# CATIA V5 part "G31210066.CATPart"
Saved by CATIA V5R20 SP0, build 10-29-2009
Part number: G31210066
Revision: 5
Definition: design
Nomenclature: G31210066
Source: made
Description: NOT SPECIFIED
Bounding box of the stored display mesh (mm): x -5 to 66, y -8 to 8, z -8 to 8
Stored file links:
  C:\Users\Raffaele\Desktop\3D X SITO CF\BOLEX\23-BUSH REF 312\G31210066.CATPart

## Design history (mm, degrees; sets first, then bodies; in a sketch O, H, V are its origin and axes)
Body1 "MANIFOLD_SOLID_BREP #14607" (main body)
  Solid1: solid without history
Body2 "MANIFOLD_SOLID_BREP #14750"
  Solid2: solid without history
Body3 "MANIFOLD_SOLID_BREP #14893"
  Solid3: solid without history
Body4 "MANIFOLD_SOLID_BREP #15036"
  Solid4: solid without history
Body5 "MANIFOLD_SOLID_BREP #15179"
  Solid5: solid without history
Body6 "MANIFOLD_SOLID_BREP #15324"
  Solid6: solid without history
Body7 "MANIFOLD_SOLID_BREP #15469"
  Solid7: solid without history
Body8 "MANIFOLD_SOLID_BREP #15614"
  Solid8: solid without history
Body9 "MANIFOLD_SOLID_BREP #15759"
  Solid9: solid without history
Body10 "MANIFOLD_SOLID_BREP #15904"
  Solid10: solid without history
Body11 "MANIFOLD_SOLID_BREP #16049"
  Solid11: solid without history
Body12 "MANIFOLD_SOLID_BREP #16194"
  Solid12: solid without history
Body13 "MANIFOLD_SOLID_BREP #16339"
  Solid13: solid without history
Body14 "MANIFOLD_SOLID_BREP #16484"
  Solid14: solid without history
Body15 "MANIFOLD_SOLID_BREP #16629"
  Solid15: solid without history
Body16 "MANIFOLD_SOLID_BREP #16774"
  Solid16: solid without history
Body17 "MANIFOLD_SOLID_BREP #16919"
  Solid17: solid without history
Body18 "MANIFOLD_SOLID_BREP #17064"
  Solid18: solid without history
Body19 "MANIFOLD_SOLID_BREP #17209"
  Solid19: solid without history
Body20 "MANIFOLD_SOLID_BREP #17354"
  Solid20: solid without history
Body21 "MANIFOLD_SOLID_BREP #17499"
  Solid21: solid without history
Body22 "MANIFOLD_SOLID_BREP #17644"
  Solid22: solid without history
Body23 "MANIFOLD_SOLID_BREP #17789"
  Solid23: solid without history
Body24 "MANIFOLD_SOLID_BREP #17934"
  Solid24: solid without history
Body25 "MANIFOLD_SOLID_BREP #18079"
  Solid25: solid without history
Body26 "MANIFOLD_SOLID_BREP #18224"
  Solid26: solid without history
Body27 "MANIFOLD_SOLID_BREP #18369"
  Solid27: solid without history
Body28 "MANIFOLD_SOLID_BREP #18514"
  Solid28: solid without history
Body29 "MANIFOLD_SOLID_BREP #18659"
  Solid29: solid without history
Body30 "MANIFOLD_SOLID_BREP #18804"
  Solid30: solid without history
Body31 "MANIFOLD_SOLID_BREP #18949"
  Solid31: solid without history
Body32 "MANIFOLD_SOLID_BREP #19094"
  Solid32: solid without history
Body33 "MANIFOLD_SOLID_BREP #19239"
  Solid33: solid without history
Body34 "MANIFOLD_SOLID_BREP #19384"
  Solid34: solid without history
Body35 "MANIFOLD_SOLID_BREP #19529"
  Solid35: solid without history
Body36 "MANIFOLD_SOLID_BREP #19674"
  Solid36: solid without history
Body37 "MANIFOLD_SOLID_BREP #19817"
  Solid37: solid without history
Body38 "MANIFOLD_SOLID_BREP #19960"
  Solid38: solid without history
Body39 "MANIFOLD_SOLID_BREP #20105"
  Solid39: solid without history
Body40 "MANIFOLD_SOLID_BREP #20250"
  Solid40: solid without history
Body41 "MANIFOLD_SOLID_BREP #20395"
  Solid41: solid without history
Body42 "MANIFOLD_SOLID_BREP #20540"
  Solid42: solid without history
Body43 "MANIFOLD_SOLID_BREP #20685"
  Solid43: solid without history
Body44 "MANIFOLD_SOLID_BREP #20830"
  Solid44: solid without history
Body45 "MANIFOLD_SOLID_BREP #20975"
  Solid45: solid without history
Body46 "MANIFOLD_SOLID_BREP #21120"
  Solid46: solid without history
Body47 "MANIFOLD_SOLID_BREP #21265"
  Solid47: solid without history
Body48 "MANIFOLD_SOLID_BREP #21410"
  Solid48: solid without history
Body49 "MANIFOLD_SOLID_BREP #21555"
  Solid49: solid without history
Body50 "MANIFOLD_SOLID_BREP #21700"
  Solid50: solid without history
Body51 "MANIFOLD_SOLID_BREP #21845"
  Solid51: solid without history
Body52 "MANIFOLD_SOLID_BREP #21990"
  Solid52: solid without history
Body53 "MANIFOLD_SOLID_BREP #22135"
  Solid53: solid without history
Body54 "MANIFOLD_SOLID_BREP #22280"
  Solid54: solid without history
Body55 "MANIFOLD_SOLID_BREP #22425"
  Solid55: solid without history
Body56 "MANIFOLD_SOLID_BREP #22570"
  Solid56: solid without history
Body57 "MANIFOLD_SOLID_BREP #22715"
  Solid57: solid without history
Body58 "MANIFOLD_SOLID_BREP #22860"
  Solid58: solid without history
Body59 "MANIFOLD_SOLID_BREP #23003"
  Solid59: solid without history
Body60 "MANIFOLD_SOLID_BREP #23146"
  Solid60: solid without history
Body61 "MANIFOLD_SOLID_BREP #23291"
  Solid61: solid without history
Body62 "MANIFOLD_SOLID_BREP #23436"
  Solid62: solid without history
Body63 "MANIFOLD_SOLID_BREP #23581"
  Solid63: solid without history
Body64 "MANIFOLD_SOLID_BREP #23726"
  Solid64: solid without history
Body65 "MANIFOLD_SOLID_BREP #23871"
  Solid65: solid without history
Body66 "MANIFOLD_SOLID_BREP #24016"
  Solid66: solid without history
Body67 "MANIFOLD_SOLID_BREP #24159"
  Solid67: solid without history
Body68 "MANIFOLD_SOLID_BREP #24302"
  Solid68: solid without history
Body69 "MANIFOLD_SOLID_BREP #24447"
  Solid69: solid without history
Body70 "MANIFOLD_SOLID_BREP #24592"
  Solid70: solid without history
Body71 "MANIFOLD_SOLID_BREP #24737"
  Solid71: solid without history
Body72 "MANIFOLD_SOLID_BREP #24882"
  Solid72: solid without history
Body73 "MANIFOLD_SOLID_BREP #25027"
  Solid73: solid without history
Body74 "MANIFOLD_SOLID_BREP #25172"
  Solid74: solid without history
Body75 "MANIFOLD_SOLID_BREP #25317"
  Solid75: solid without history
Body76 "MANIFOLD_SOLID_BREP #25462"
  Solid76: solid without history
Body77 "MANIFOLD_SOLID_BREP #25607"
  Solid77: solid without history
Body78 "MANIFOLD_SOLID_BREP #25752"
  Solid78: solid without history
Body79 "MANIFOLD_SOLID_BREP #25897"
  Solid79: solid without history
Body80 "MANIFOLD_SOLID_BREP #26042"
  Solid80: solid without history
Body81 "MANIFOLD_SOLID_BREP #26187"
  Solid81: solid without history
Body82 "MANIFOLD_SOLID_BREP #26332"
  Solid82: solid without history
Body83 "MANIFOLD_SOLID_BREP #26477"
  Solid83: solid without history
Body84 "MANIFOLD_SOLID_BREP #26622"
  Solid84: solid without history
Body85 "MANIFOLD_SOLID_BREP #26767"
  Solid85: solid without history
Body86 "MANIFOLD_SOLID_BREP #26912"
  Solid86: solid without history
Body87 "MANIFOLD_SOLID_BREP #27057"
  Solid87: solid without history
Body88 "MANIFOLD_SOLID_BREP #27202"
  Solid88: solid without history
Body89 "MANIFOLD_SOLID_BREP #27345"
  Solid89: solid without history
Body90 "MANIFOLD_SOLID_BREP #27488"
  Solid90: solid without history
Body91 "MANIFOLD_SOLID_BREP #27633"
  Solid91: solid without history
Body92 "MANIFOLD_SOLID_BREP #27778"
  Solid92: solid without history
Body93 "MANIFOLD_SOLID_BREP #27923"
  Solid93: solid without history
Body94 "MANIFOLD_SOLID_BREP #28068"
  Solid94: solid without history
Body95 "MANIFOLD_SOLID_BREP #28213"
  Solid95: solid without history
Body96 "MANIFOLD_SOLID_BREP #28358"
  Solid96: solid without history
Body97 "MANIFOLD_SOLID_BREP #28501"
  Solid97: solid without history
Body98 "MANIFOLD_SOLID_BREP #28644"
  Solid98: solid without history
Body99 "MANIFOLD_SOLID_BREP #28789"
  Solid99: solid without history
Body100 "MANIFOLD_SOLID_BREP #28934"
  Solid100: solid without history
Body101 "MANIFOLD_SOLID_BREP #29079"
  Solid101: solid without history
Body102 "MANIFOLD_SOLID_BREP #29224"
  Solid102: solid without history
Body103 "MANIFOLD_SOLID_BREP #29369"
  Solid103: solid without history
Body104 "MANIFOLD_SOLID_BREP #29514"
  Solid104: solid without history
Body105 "MANIFOLD_SOLID_BREP #29659"
  Solid105: solid without history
